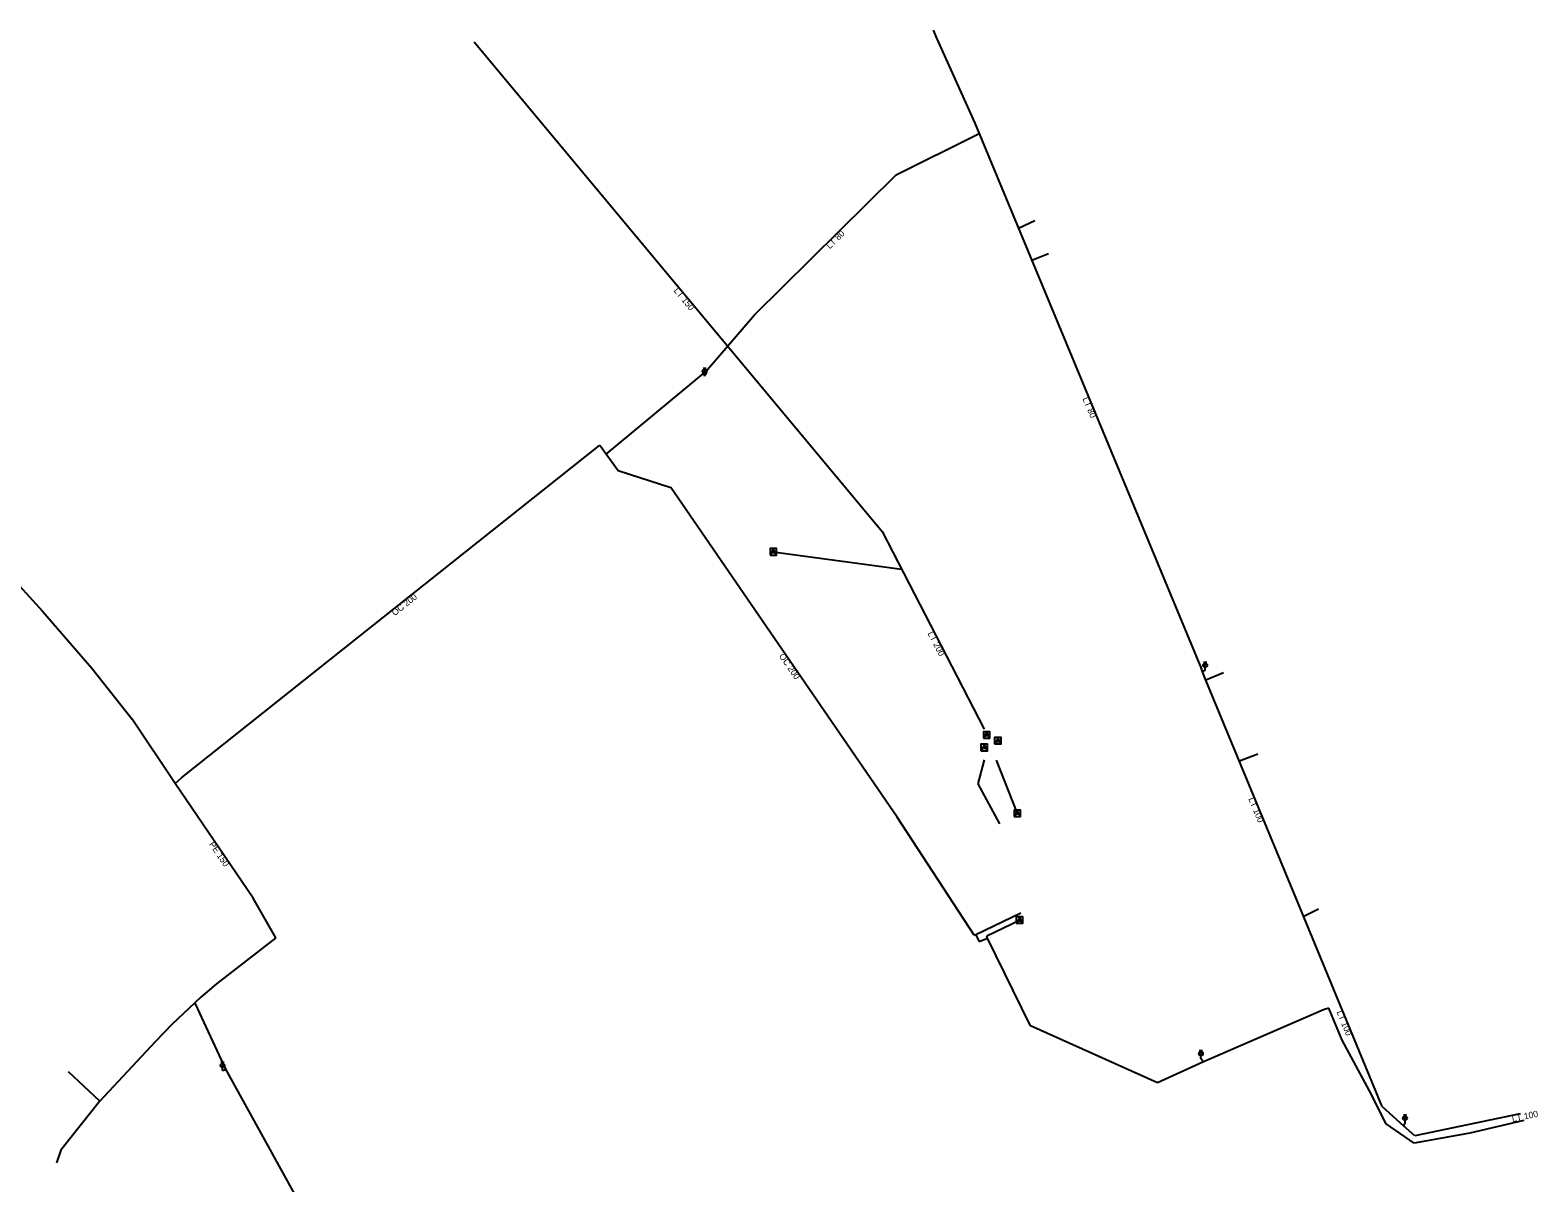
# Model space of a CAD drawing. Extents: x -513141 to -512601, y -1130827 to -1130115.
# Drawn here: x -512832.4 to -512600.9, y -1130695.6 to -1130518.5 of the extents above; entities that cross this region are included whole.
import ezdxf

# ---------------------------------------------------------------- set-up
doc = ezdxf.new("R2010")
doc.units = 0
for name, color, linetype in [('Default', 7, 'Continuous'), ('MoLevel 10', 7, 'Continuous'), ('MoLevel 12', 7, 'Continuous'), ('MoLevel 13', 7, 'Continuous'), ('MoLevel 15', 7, 'Continuous'), ('MoLevel 32', 7, 'Continuous')]:
    doc.layers.add(name, color=color, linetype=linetype)

# ---------------------------------------------------------------- blocks, each defined once
blk = doc.blocks.new('0.05')
at = {"layer": 'Default'}
for p, q in [((-0.01, 0.05), (0.01, 0.05)), ((-0.009, 0.021), (0.009, 0.039)), ((0, 0.0425), (0, 0.05)), ((0, 0), (0, 0.0175))]:
    blk.add_line(p, q, dxfattribs=at)
blk.add_circle((0, 0.03), 0.0125, dxfattribs=at)
blk = doc.blocks.new('0.13')
at = {"layer": 'Default'}
for p, q in [((0, 0.04), (-0.035, -0.035)), ((0, 0.04), (0.035, -0.035)), ((-0.0235, -0.0095), (0.0235, -0.0095))]:
    blk.add_line(p, q, dxfattribs=at)
blk.add_lwpolyline([(-0.05, -0.05), (0.05, -0.05), (0.05, 0.05), (-0.05, 0.05), (-0.05, -0.05)], dxfattribs=at)

msp = doc.modelspace()

# ---------------------------------------------------------------- linework, layer by layer
at = {"layer": 'MoLevel 10'}
for p, q in [((-512693.77, -1130518.5), (-512693.19, -1130519.85)), ((-512764.23, -1130520.31), (-512701.61, -1130595.54)), ((-512693.19, -1130519.85), (-512693.06, -1130519.82)), ((-512693.19, -1130519.85), (-512687.35, -1130532.78)), ((-512687.35, -1130532.78), (-512652.52, -1130616.69)), ((-512699.46, -1130540.72), (-512686.98, -1130534.52)), ((-512686.98, -1130534.52), (-512686.69, -1130534.38)), ((-512721.17, -1130562.25), (-512699.46, -1130540.72)), ((-512728.72, -1130570.97), (-512721.17, -1130562.25)), ((-512743.96, -1130583.64), (-512728.72, -1130570.97)), ((-512728.55, -1130571.21), (-512728.85, -1130571.68)), ((-512728.72, -1130570.97), (-512728.55, -1130571.21)), ((-512809.13, -1130633.31), (-512744.97, -1130582.24)), ((-512744.97, -1130582.24), (-512742.14, -1130586.17)), ((-512742.14, -1130586.17), (-512734.05, -1130588.78)), ((-512699.3, -1130639.42), (-512734.05, -1130588.78)), ((-512843.65, -1130593.36), (-512830.55, -1130607.78)), ((-512701.61, -1130595.54), (-512685.93, -1130625.9)), ((-512718.31, -1130598.64), (-512698.62, -1130601.32)), ((-512830.55, -1130607.78), (-512822.99, -1130616.5)), ((-512822.99, -1130616.5), (-512816.79, -1130624.33)), ((-512651.86, -1130618.35), (-512652.52, -1130616.69)), ((-512652.4, -1130616.99), (-512651.98, -1130616.84)), ((-512637.05, -1130654.09), (-512651.86, -1130618.35)), ((-512810.18, -1130634.21), (-512816.79, -1130624.33)), ((-512686.86, -1130634.29), (-512685.89, -1130630.58)), ((-512684.07, -1130630.63), (-512680.83, -1130638.82)), ((-512810.18, -1130634.21), (-512809.13, -1130633.31)), ((-512798.22, -1130651.85), (-512810.18, -1130634.21)), ((-512683.53, -1130640.43), (-512686.86, -1130634.29)), ((-512687.48, -1130657.51), (-512699.3, -1130639.42)), ((-512794.72, -1130657.92), (-512798.22, -1130651.85)), ((-512687.22, -1130657.44), (-512680.28, -1130654.08)), ((-512685.5, -1130657.61), (-512680.49, -1130655.21)), ((-512624.78, -1130683.83), (-512637.05, -1130654.09)), ((-512794.72, -1130657.92), (-512803.82, -1130665.02)), ((-512687.48, -1130657.51), (-512687.22, -1130657.44)), ((-512687.22, -1130657.44), (-512687.02, -1130657.85)), ((-512687.02, -1130657.85), (-512686.71, -1130658.48)), ((-512685.41, -1130658.01), (-512685.5, -1130657.61)), ((-512686.71, -1130658.48), (-512685.41, -1130658.01)), ((-512678.82, -1130671.45), (-512685.41, -1130658.01)), ((-512803.82, -1130665.02), (-512806.24, -1130667.07)), ((-512807.17, -1130667.94), (-512810.69, -1130671.27)), ((-512807.06, -1130668.06), (-512807.17, -1130667.94)), ((-512802.41, -1130678.09), (-512807.06, -1130668.06)), ((-512633.81, -1130668.98), (-512652.34, -1130677.05)), ((-512632.99, -1130668.72), (-512633.81, -1130668.98)), ((-512630.95, -1130673.68), (-512632.99, -1130668.72)), ((-512810.69, -1130671.27), (-512813.18, -1130673.85)), ((-512659.32, -1130680.19), (-512678.82, -1130671.45)), ((-512813.18, -1130673.85), (-512821.78, -1130683.06)), ((-512626.75, -1130681.45), (-512630.95, -1130673.68)), ((-512652.4, -1130676.83), (-512652.63, -1130676.49)), ((-512802.91, -1130678.3), (-512802.62, -1130678.2)), ((-512802.62, -1130678.2), (-512802.41, -1130678.09)), ((-512759.17, -1130756.39), (-512802.41, -1130678.09)), ((-512652.34, -1130677.05), (-512659.32, -1130680.19)), ((-512652.34, -1130677.05), (-512652.4, -1130676.83)), ((-512821.78, -1130683.06), (-512827.76, -1130690.57)), ((-512624.18, -1130686.51), (-512626.75, -1130681.45)), ((-512624.78, -1130683.83), (-512621.49, -1130686.83)), ((-512603.61, -1130685), (-512619.77, -1130688.38)), ((-512619.89, -1130689.46), (-512624.18, -1130686.51)), ((-512621.41, -1130686.59), (-512621.49, -1130686.83)), ((-512619.77, -1130688.38), (-512621.49, -1130686.83)), ((-512621.28, -1130686.4), (-512621.41, -1130686.59)), ((-512611.33, -1130687.96), (-512619.89, -1130689.46)), ((-512603.01, -1130685.99), (-512611.33, -1130687.96)), ((-512827.76, -1130690.57), (-512828.38, -1130692.49))]:
    msp.add_line(p, q, dxfattribs=at)
msp.add_lwpolyline([(-512806.24, -1130667.07), (-512807.11, -1130667.89), (-512807.17, -1130667.94)], dxfattribs=at)
at = {"layer": 'MoLevel 15'}
for p, q in [((-512678.16, -1130547.79), (-512680.62, -1130548.99)), ((-512676.06, -1130552.87), (-512678.59, -1130553.89)), ((-512649.17, -1130617.24), (-512651.86, -1130618.35)), ((-512643.89, -1130629.7), (-512646.7, -1130630.81)), ((-512634.55, -1130653.56), (-512636.82, -1130654.64)), ((-512821.73, -1130683.02), (-512826.57, -1130678.55))]:
    msp.add_line(p, q, dxfattribs=at)

# ---------------------------------------------------------------- block references
at = {"layer": 'MoLevel 12', "xscale": 25, "yscale": 25}
for p in [(-512728.85, -1130571.68), (-512651.98, -1130616.84), (-512652.63, -1130676.49), (-512802.91, -1130678.3), (-512621.28, -1130686.4)]:
    msp.add_blockref('0.05', p, dxfattribs=at)
at = {"layer": 'MoLevel 13', "xscale": 10, "yscale": 10}
for p in [(-512718.31, -1130598.64), (-512685.54, -1130626.77), (-512683.81, -1130627.66), (-512685.92, -1130628.69), (-512680.83, -1130638.82), (-512680.49, -1130655.21)]:
    msp.add_blockref('0.13', p, dxfattribs=at)

# ---------------------------------------------------------------- texts
at = {"layer": 'MoLevel 32'}
for s, rotation, p in [('LT 80', 44.7615, (-512709.63, -1130552.18)), ('LT 150', 309.7733, (-512733.67, -1130558.55)), ('LT 80', 292.5427, (-512670.84, -1130575.11)), ('OC 200', 38.519, (-512776.44, -1130608.54)), ('LT 200', 297.315, (-512694.64, -1130611.17)), ('OC 200', 304.455, (-512717.48, -1130614.65)), ('LT 100', 292.5082, (-512645.36, -1130636.59)), ('PE 150', 304.1329, (-512805.01, -1130643.58)), ('LT 100', 292.4199, (-512631.82, -1130669.33)), ('LT 100', 11.805, (-512604.75, -1130686.24))]:
    msp.add_text(s, height=0.975, rotation=rotation, dxfattribs=at).set_placement(p)

doc.saveas('drawing.dxf')
